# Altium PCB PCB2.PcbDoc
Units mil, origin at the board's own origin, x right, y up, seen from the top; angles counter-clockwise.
Board outline 2100 x 2751.23 mil, 2 copper layers (Top Layer, Bottom Layer); 38 components, 9 nets, 65 pads, 13 vias.
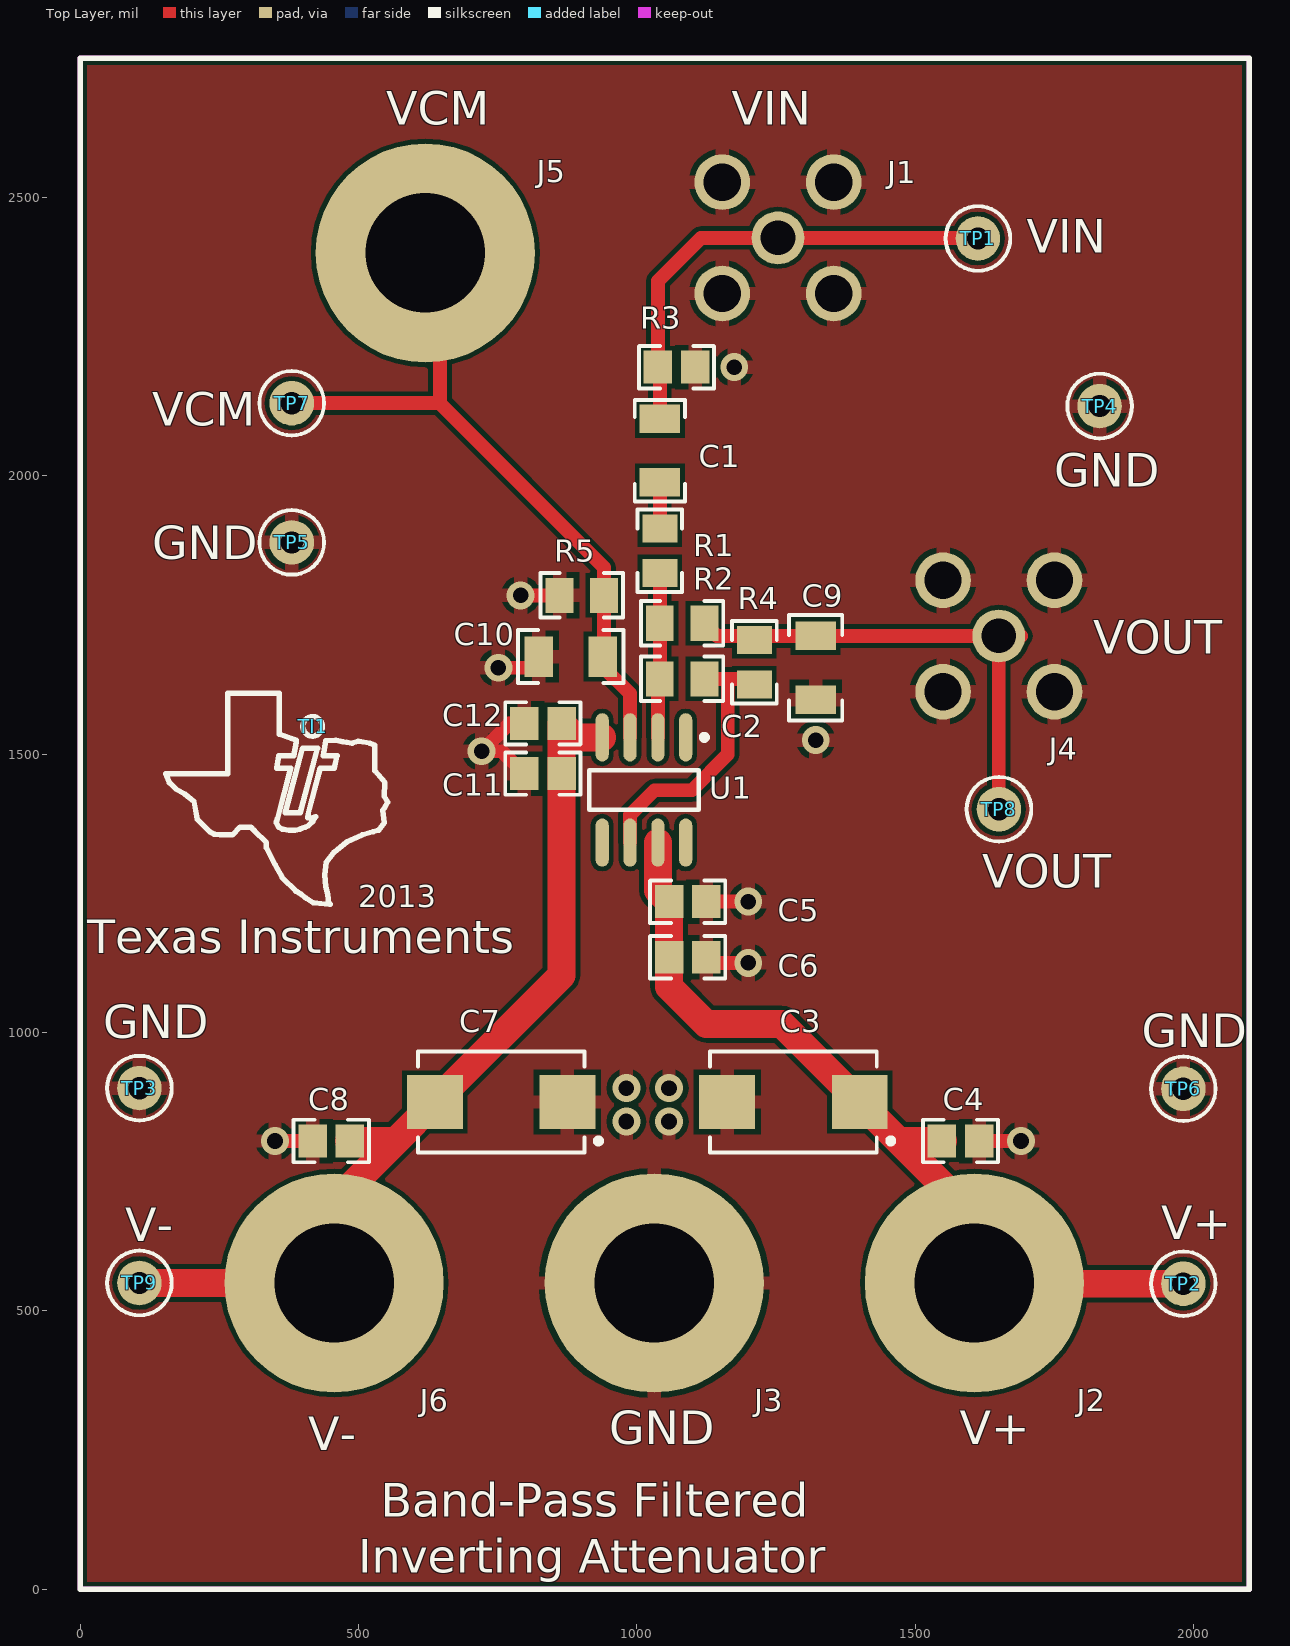
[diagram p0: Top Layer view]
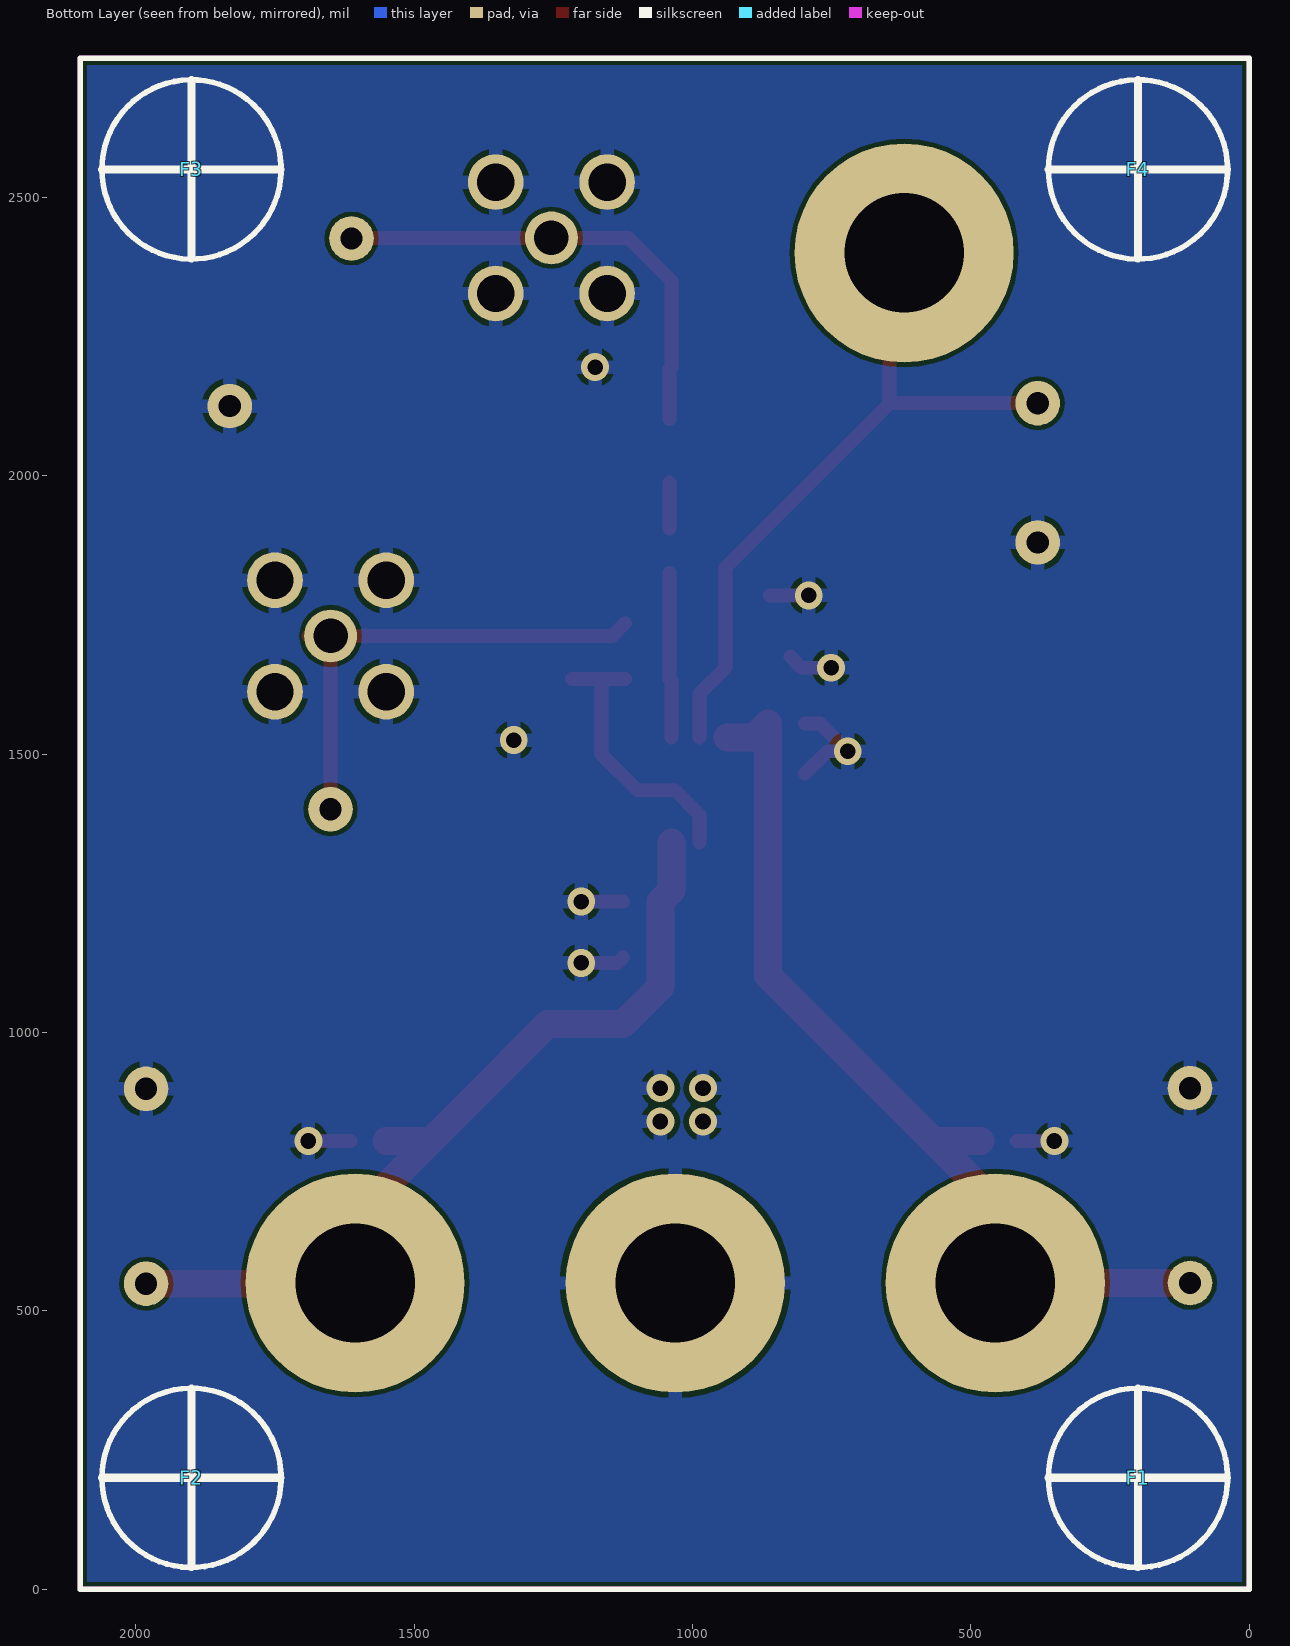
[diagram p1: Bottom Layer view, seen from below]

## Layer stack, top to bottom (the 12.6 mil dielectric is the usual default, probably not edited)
Top Layer: signal copper 1.4
Dielectric: dielectric 12.6, FR-4, Dk 4.8
Bottom Layer: signal copper 1.4

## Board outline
0,0 2100,-1.23 2100,2750 0,2750

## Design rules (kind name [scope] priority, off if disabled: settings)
Clearance [All] p1: gap=8
FabricationTestPointUsage TestPointUsage [All] p1: valid=0 allowmultiple=FALSE
FabricationTestpoint Testpoint [All] p1: side=3 testpointundercomponent=TRUE minsize=40 maxsize=100 preferedsize=60 minholesize=0 maxholesize=40 preferedholesize=32 testpointgrid=1 allowsidetop=TRUE allowsidebottom=TRUE usegrid=TRUE gridtolerance=0.01
HoleSize [All] p1: absolutevalues=TRUE maxlimit=246 minlimit=1 maxpercent=80.000 minpercent=20.000
PolygonConnect [All] p1: connectstyle=Relief reliefconductorwidth=25 reliefentries=4 polygonreliefangle="90 Angle" airgapwidth=10
RoutingVias [All] p1: holewidth=28 width=50 viastyle="Through Hole" minholewidth=28 minwidth=50 maxholewidth=28 maxwidth=50
SilkscreenOverComponentPads [All] p1: minsilkscreentomaskgap=10
SolderMaskExpansion [All] p1: expansion=4
Width [All] p1: maxlimit=100 minlimit=8 preferedwidth=15
24 further rules are at their usual default settings.

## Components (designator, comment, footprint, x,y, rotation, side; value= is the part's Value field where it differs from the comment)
C1 "GRM31CR72A105KA01L" 1206 1041.19,2045 r90 top
C2 "08055A122JAT2A" 0805_HV 1081.19,1635 r180 top
C3 "TPSE106K050R0400" 7343-43 1281.19,875 r180 top
C4 "GRM21BR71H104KA01L" 0805 1581.19,805 r0 top
C5 "GRM2165C1H101JA01D" 0805 1091.19,1235 r0 top
C6 "GRM21BR71H104KA01L" 0805 1091.19,1135 r0 top
C7 "TPSE106K050R0400" 7343-43 756.19,875 r180 top
C8 "GRM21BR71H104KA01L" 0805 451.19,805 r0 top
C9 "GRM31C5C1H683JA01L" 1206 1321.19,1655 r270 top
C10 "CGJ5L2C0G1H104J160AA" 1206 881.19,1675 r180 top
C11 "GRM2165C1H101JA01D" 0805 831.19,1465 r180 top
C12 "GRM21BR71H104KA01L" 0805 831.19,1555 r180 top
F1 "PartNumber" Rubber_Foot 200,200 r180 bottom
F2 "PartNumber" Rubber_Foot 1900,200 r180 bottom
F3 "PartNumber" Rubber_Foot 1900,2550 r180 bottom
F4 "PartNumber" Rubber_Foot 200,2550 r180 bottom
J1 "142-0701-201" Johnson_142-0701-20x 1253.46,2427.24 r0 top
J2 "V+" Keystone_575-4 1606.19,550 r90 top
J3 "GND" Keystone_575-4 1031.19,550 r90 top
J4 "142-0701-201" Johnson_142-0701-20x 1650,1712.09 r90 top
J5 "VCM" Keystone_575-4 620,2400 r90 top
J6 "V-" Keystone_575-4 456.19,550 r90 top
R1 "RG2012P-104-B-T5" 0805_HV 1041.19,1865 r270 top
R2 "RG2012P-102-B-T5" 0805_HV 1081.19,1735 r0 top
R3 "49.9R" 0805 1071.19,2195 r0 top
R4 "RJ0805FRE078R2L" 0805_HV 1211.19,1665 r90 top
R5 "CRCW08051K00FKEA" 0805_HV 901.19,1785 r0 top
TI1 "Texas Instruments logo" "TI LOGO" 417.73,1550 r0 top
TP1 "Vin" Keystone5002 1612.56,2426.01 r0 top
TP2 "V+" Keystone5000 1981.5,548.77 r90 top
TP3 "GND" Keystone5001 106.5,900 r90 top
TP4 "GND" Keystone5001 1831.19,2125 r90 top
TP5 "GND" Keystone5001 380.12,1880.18 r90 top
TP6 "GND" Keystone5001 1981.5,898.77 r90 top
TP7 "VCM" Keystone5002 380.12,2130.18 r90 top
TP8 "Vout" Keystone5002 1650.31,1400.86 r90 top
TP9 "V-" Keystone5004 106.5,550 r90 top
U1 "OPA627AU" 182H_N 1012.69,1435.51 r270 top

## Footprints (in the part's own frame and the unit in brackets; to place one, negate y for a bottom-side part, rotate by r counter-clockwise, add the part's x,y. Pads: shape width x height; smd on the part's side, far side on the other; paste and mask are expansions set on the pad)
182H_N [mm] "SOIC, 8-Leads, Body 4.9x3.9mm, Pitch 1.27mm, IPC Medium Density"
  oval 2.2x0.6 smd: 1(-2.4,1.905) 2(-2.4,0.635) 3(-2.4,-0.635) 4(-2.4,-1.905) 5(2.4,-1.905) 6(2.4,-0.635) 7(2.4,0.635) 8(2.4,1.905)
  silkscreen extent -2.52,-2.5 0.9,2.88, body extent -1.95,-2.45 1.95,2.45, height 1.75
0805 [mm] "0805 from SM-752 data"
  rect 1.3x1.5 smd: 1(-0.85,0) 2(0.85,0)
  silkscreen extent -1.72,-0.97 1.72,0.97, body extent -1.1,-0.72 1.1,0.72, height 1.1
0805_HV [mil] "0805 with 30mil clearance between pads"
  rect 50x63 smd: 1(-40,0) 2(40,0)
  silkscreen extent -74,-40 74,40, body extent -43,-29 43,29, height 43
1206 [mm] "1206 from SM-752 data"
  rect 1.3x1.85 smd: 1(-1.45,0) 2(1.45,0)
  silkscreen extent -2.32,-1.14 2.32,1.14, body extent -1.7,-0.9 1.7,0.9, height 1.35
7343-43 [mm] "Medium density IPC based on Kemet T495 series"
  rect 2.55x2.45 smd: 1(-3.025,0) 2(3.025,0)
  silkscreen extent -4.56,-2.3 3.8,2.3, body extent -3.8,-2.3 3.8,2.3, height 4.3
Johnson_142-0701-20x [mil] "Johnson Components recommended land pattern"
  round 95 hole 62: 1(0,0)
  round 100 hole 67: 2(100,100) 3(100,-100) 4(-100,-100) 5(-100,100)
  body extent -156,-156 156,156, height 375
Keystone5000 [mil] "For Keystone 500x miniature loop terminals"
  round 80 hole 40: 1(0,0)
  silkscreen extent -58,-58 58,58, body extent -49,-49 49,49, height 182
Keystone5001 [mil] "For Keystone 500x miniature loop terminals"
  round 80 hole 40: 1(0,0)
  silkscreen extent -58,-58 58,58, body extent -49,-49 49,49, height 182
Keystone5002 [mil] "For Keystone 500x miniature loop terminals"
  round 80 hole 40: 1(0,0)
  silkscreen extent -58,-58 58,58, body extent -49,-49 49,49, height 182
Keystone5004 [mil] "For Keystone 500x miniature loop terminals"
  round 80 hole 40: 1(0,0)
  silkscreen extent -58,-58 58,58, body extent -49,-49 49,49, height 182
Keystone_575-4 [mm] "Banana Jack"
  round 10 hole 5.45: 1(0,0)
  body extent -3.95,-3.95 3.92,3.93, height 2.36
Rubber_Foot [mil] "Rubber Foot"
  silkscreen extent -161,-161 161,161
"TI LOGO" [mil] "TI BUG"
  silkscreen extent -264,-320 135,59

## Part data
C1: "CAP, CERM, 1uF, 100V, +/-10%, X7R, 1206"
C2: "CAP, CERM, 1200pF, 50V, +/-5%, C0G/NP0, 0805"
C3 C7: "CAP, TANT, 10uF, 50V, +/-10%, 0.4 ohm, 7343-43 SMD"
C4 C6 C8 C12: "CAP, CERM, 0.1uF, 50V, +/-10%, X7R, 0805"
C5 C11: "CAP, CERM, 100pF, 50V, +/-5%, C0G/NP0, 0805"
C9: "CAP, CERM, 0.068uF, 50V, +/-5%, C0G/NP0, 1206"
C10: library part 12065C104KAT2A, "CAP CER 0.1UF 50V 5% NP0 1206"
F1 F2 F3 F4: library part SJ61A1, "BUMPON CYLINDRICAL .312X.200 BLK"
J1 J4: "Connector, TH, SMA"
J2 J3 J5 J6: library part 575-4, "Standard Banana Jack, Uninsulated, 5.5mm"
R1: "RES, 100k ohm, 0.1%, 0.125W, 0805"
R2: "RES, 1.00k ohm, 0.1%, 0.125W, 0805"
R3: library part CRCW080549R9FKEA, "RES 49.9 OHM 0.20W 0.1% 0805"
R4: library part CRCW08058R20JNEA, "RES 8.2 OHM 1/10W 1% 0805 SMD"
R5: "RES, 1.00k ohm, 1%, 0.125W, 0805"
TI1: library part "TI LOGO", "TI BUG"
TP1 TP7 TP8: library part 5002, "Test Point, TH, Miniature, White"
TP2: library part 5000, "Test Point, TH, Miniature, Red"
TP3 TP4 TP5 TP6: library part 5001, "Test Point, TH, Miniature, Black"
TP9: library part 5004, "Test Point, TH, Miniature, Yellow"
U1: "Precision High-Speed Difet Operational Amplifiers"

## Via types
v1: diameter 50, hole 28, Top Layer to Bottom Layer, 13 vias

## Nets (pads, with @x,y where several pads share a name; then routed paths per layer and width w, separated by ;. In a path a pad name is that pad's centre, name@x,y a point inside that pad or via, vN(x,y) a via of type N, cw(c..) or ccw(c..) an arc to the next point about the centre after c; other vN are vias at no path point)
GND: C3.2 C4.2 C5.2 C6.2 C7.1 C8.1 C9.2 C10.2 C11.2 C12.2 J1.2 J1.3 J1.4 J1.5 J3.1 J4.2 J4.3 J4.4 J4.5 R3.2 R5.1 TP3.1 TP4.1 TP5.1 TP6.1 | length 639.5
  Top Layer w25: v1(350,805) C8.1 ; v1(751.19,1655) 804.1,1655 C10.2 ; v1(791.19,1785) R5.1 ; C11.2 757.73,1505 v1(721.19,1505) 771.19,1555 C12.2 ; C6.2 1134.65,1125 v1(1200,1125) ; C5.2 v1(1200,1235) ; C4.2 v1(1690,805)
  other v1: 981.19,840 1057.73,840 981.19,900 1057.73,900 1321.19,1525 1175,2195
NetC1_1: C1.1 R1.1 | length 82.9
  Top Layer w25: R1.1 C1.1
NetC1_2: C1.2 J1.1 R3.1 TP1.1 | length 856
  Top Layer w25: C1.2 1041.19,2191.54 R3.1 1037.73,2350 1114.96,2427.24 J1.1 TP1.1@1612.38,2427.24
NetC2_1: C2.1 R4.1 U1.6 | length 501.5
  Top Layer w25: U1.6 987.69,1390.83 1031.86,1435 1099.19,1435 1163.19,1499 1163.19,1634 1164.19,1635 ; C2.1 1164.19,1635 ; R4.1@1216.19,1635 1164.19,1635
NetC2_2: C2.2 R1.2 R2.1 U1.2 | length 296.5
  Top Layer w25: U1.2 1037.69,1631.5 C2.2 R1.2
NetC9_1: C9.1 J4.1 R2.2 R4.2 TP8.1 | length 889.5
  Top Layer w25: R2.2 1144.1,1712.09 1336.19,1712.09 J4.1@1690,1712.09 ; TP8.1@1650,1400.86 J4.1
NetC10_1: C10.1 J5.1 R5.2 TP7.1 U1.3 | length 1288.4
  Top Layer w25: TP7.1 646.01,2130.18 646.19,2130 ; J5.1 646.19,2373.81 646.19,2130 ; U1.3 987.69,1608.5 941.19,1655 941.19,1835 646.19,2130
V1+: C3.1 C4.1 C5.1 C6.1 J2.1 TP2.1 U1.7 | length 1561.2
  Top Layer w50: U1.7 1037.69,1255.04 C5.1 C6.1 1057.73,1081.93 1124.65,1015 1260.28,1015 C3.1 1470.28,805 ; C4.1@1549.69,805 1470.28,805 ; TP2.1 1607.42,548.77 J2.1 1606.19,669.09 1470.28,805
V1-: C7.2 C8.2 C11.1 C12.1 J6.1 TP9.1 U1.4 | length 1691.7
  Top Layer w50: TP9.1 J6.1 456.19,694.09 567.1,805 ; C8.2@482.69,805 567.1,805 ; U1.4 889.65,1530 C12.1 C11.1 864.65,1102.56 C7.2 567.1,805
pads on no net: U1.1 U1.5 U1.8

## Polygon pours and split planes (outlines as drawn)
GND on Top Layer "GND" (solid, remove dead copper, pour order 4): 0,0 0,2750 2100,2750 2100,0 0,0
GND on Bottom Layer "GND" (solid, remove dead copper, pour order 2): 0,0 0,2743.12 2093,2743.12 2100,2750 2100,0 7,0

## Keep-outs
Keep-Out Layer:
  lines w10: 0,0 2100,0 2100,2750 0,2750 0,0

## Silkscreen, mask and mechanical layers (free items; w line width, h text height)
Top Overlay:
  lines w10: 0,2750 2100,2750 ; 0,2750 0,0 2100,0 2100,2750 ; 0,2750 2100,2750
  text "VCM" at 550,2630 h60
  text "VIN" at 1170,2630 h60
  text "VIN" at 1700,2400 h60
  text "VOUT" at 1820,1680 h60
  text "VOUT" at 1620,1260 h60
  text "2013" at 500,1225 h40
  text "Texas Instruments" at 13.25,1142.65 h60
  text "GND" at 950,260 h60
  text "V+" at 1580,260 h60
  text "V-" at 410,250 h60
  text "Band-Pass Filtered" at 540,130 h60
  text "Inverting Attenuator" at 500,30 h60
Bottom Overlay:
  lines w10: 0,2750 2100,2750 ; 0,2750 2100,2750 ; 0,2750 0,0 2100,0 2100,2750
